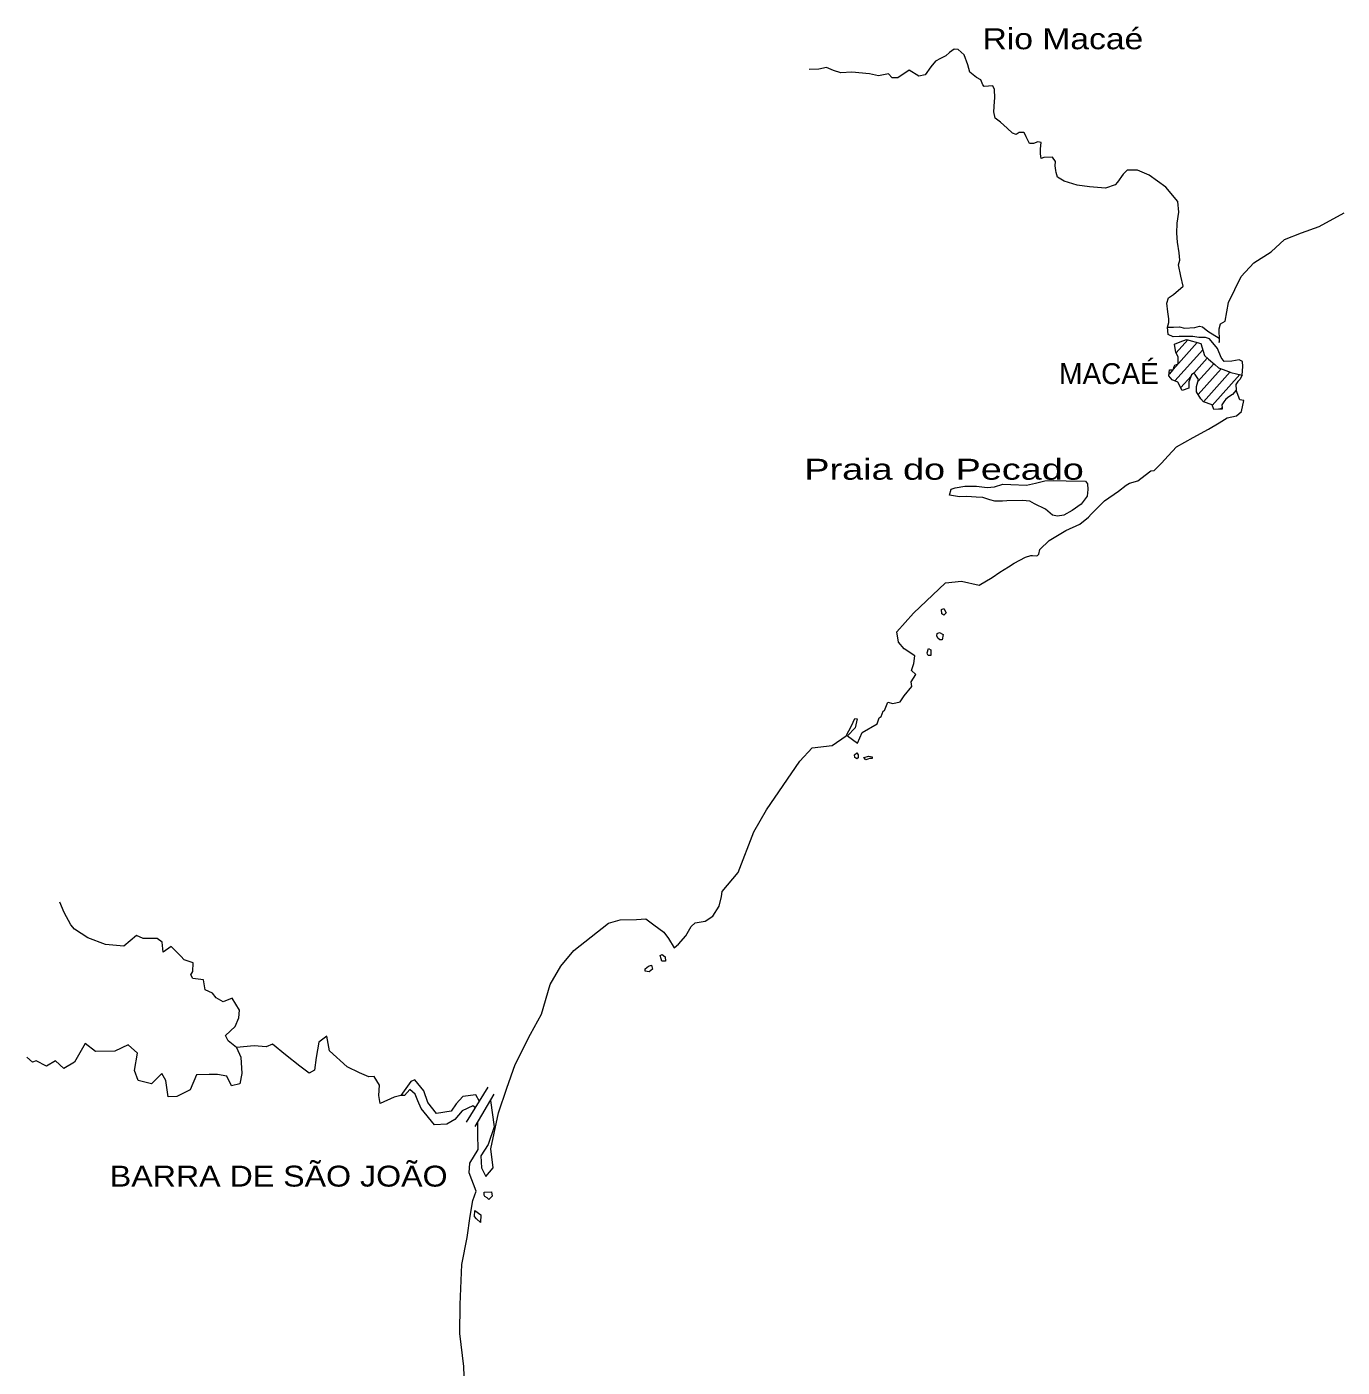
# Model space of a CAD drawing. Extents: x 47169 to 972804, y 7447977 to 9608469.
# Drawn here: x 178508 to 218240, y 7492492 to 7532969 of the extents above; entities that cross this region are included whole.
import ezdxf

# ---------------------------------------------------------------- set-up
doc = ezdxf.new("R2010")
doc.units = 0
doc.header["$LTSCALE"] = 270
doc.layers.add('1', color=7, linetype='Continuous', lineweight=13)
doc.layers.add('3', color=7, linetype='Continuous')

msp = doc.modelspace()

# ---------------------------------------------------------------- linework, layer by layer
at = {"layer": '1'}
for p, q in [((213862.1, 7523435.8), (213135, 7522624.4)), ((214031.1, 7523217.2), (213182.5, 7522281.7)), ((213582.2, 7523519.2), (213228.8, 7523124.8)), ((214159.4, 7522964.7), (213755.4, 7522513.9)), ((214358.4, 7522791), (213883.8, 7522261.4)), ((213124.9, 7522613.1), (213014, 7522478)), ((213674.6, 7522423.8), (213361.6, 7522074.4)), ((214588, 7522640.1), (213891.2, 7521862.6)), ((214857.7, 7522545.4), (214049.8, 7521643.9)), ((215147.6, 7522473.1), (214309.4, 7521537.8)), ((214609.6, 7521465.8), (214569.2, 7521420.7)), ((191788.1, 7499889.7), (192446.3, 7500944.8)), ((192048, 7499761.9), (192625.5, 7500737.8))]:
    msp.add_line(p, q, dxfattribs=at)
for points in [[(215220.2, 7522452.3), (215236.1, 7522707.5), (215233.2, 7522862.6), (215129.2, 7522916.1), (214903.3, 7522867.6), (214676.6, 7522863.4), (214581.6, 7522983.6), (214473.5, 7523258.6), (214231.2, 7523542.3), (214106.7, 7523584.3), (213910.8, 7523591.8), (213724.7, 7523621.6), (213508.3, 7523617.6), (213312.5, 7523614), (213137.3, 7523610.7), (212981.5, 7523674.4), (212967.1, 7523895.7), (213005.7, 7524040.5), (213003.6, 7524151.3), (212968.8, 7524361.2), (212943.3, 7524626.7), (212991.9, 7524782.8), (213144.6, 7524885.4), (213439, 7525134.6), (213361.1, 7525443.5), (213292.9, 7525785.8), (213331.7, 7525919.5), (213317.3, 7526140.9), (213270.1, 7526461.4), (213244.4, 7526738), (213259.5, 7527037.5), (213304.9, 7527370.8), (213278.3, 7527691.7), (212909.4, 7528128.2), (212407.9, 7528484.6), (212054.3, 7528644.3), (211745.1, 7528638.5), (211623.7, 7528514.4), (211452.8, 7528278.5), (211382, 7528199.6), (211095.3, 7528094.5), (210609.8, 7528140.9), (210237.7, 7528189.3), (209843.7, 7528303.9), (209645.4, 7528433.2), (209601.7, 7528565.4), (209590.1, 7528631.6), (209566.8, 7528775.3), (209585.2, 7528897.5), (209489.9, 7529028.7), (209232.2, 7529023.9), (209150.4, 7528989.1), (209127, 7529132.8), (209124.1, 7529287.9), (209151.5, 7529476.8), (209048, 7529497), (208914.9, 7529450.2), (208791.1, 7529447.9), (208694.6, 7529645.6), (208641, 7529755.4), (208609.7, 7529777), (208486, 7529774.6), (208394.2, 7529717.5), (208280, 7529759.7), (208122.5, 7529911.9), (207923.2, 7530085.5), (207755.8, 7530215.3), (207721.3, 7530403.1), (207736.1, 7530713.7), (207744.4, 7530824.7), (207739.6, 7531079.5), (207685.9, 7531189.3), (207428.6, 7531162.3), (207386.3, 7531216.9), (207321.5, 7531370.8), (207196.6, 7531435), (206997.6, 7531597.5), (206931.5, 7531817.9), (206822.6, 7532126.2), (206644.1, 7532289), (206515.2, 7532292.2), (206374.6, 7532196.4), (206265.3, 7532087.9), (206103.7, 7532016.2), (205958.9, 7531929.2)], [(205958.9, 7531929.2), (205810.5, 7531755.7), (205647, 7531514.3), (205452.7, 7531478.5), (205160.5, 7531661.4), (204814.1, 7531433.2), (204649.2, 7531430), (204533.5, 7531549.8), (204235.5, 7531488.7), (203966.2, 7531550), (203429, 7531595.2), (203099.3, 7531577.8), (202871, 7531651.1), (202663.1, 7531735.8), (202426.8, 7531686.9), (202138.1, 7531681.4)], [(212967.1, 7523895.7), (213142.3, 7523899), (213327.6, 7523913.5), (213472.6, 7523871.9), (213791.9, 7523888.8), (213925.2, 7523924.5), (214018.4, 7523904.1), (214185.7, 7523774.2), (214519.3, 7523569.8), (214521.8, 7523436.8), (214531.2, 7523481.3), (214524.5, 7523846.9), (214562.9, 7524002.8), (214705.7, 7524083), (214808.9, 7524639), (215186, 7525432.8), (215570.3, 7525838.8), (216090, 7526169.7), (216495.5, 7526542.8), (217007.2, 7526751.7), (217539.9, 7526938.7), (218295.3, 7527351.4)], [(206260.7, 7516179.2), (206737.8, 7516228.2), (207269.7, 7516108.6), (207667.2, 7516337.8), (207901.2, 7516497.4), (208155.7, 7516657.3), (208328.7, 7516771.4), (208675.6, 7516955.3), (208839.6, 7517002.7), (208880.8, 7517003.5), (209004.6, 7516994.8), (209035.3, 7517006.4), (209075.8, 7517040.4), (209104, 7517185), (209387.4, 7517456.4), (209897.1, 7517754.1), (210315.9, 7517950.4), (210579.7, 7518165.9), (210660.5, 7518256), (211065.3, 7518651.5), (211482.2, 7518947.5), (211715.9, 7519129.1), (211817.8, 7519186.5), (212063.8, 7519257.5), (212287.4, 7519427.9), (212460, 7519564.1), (212563, 7519566), (212785.6, 7519791.8), (212987.5, 7520017.2), (213240.1, 7520287.9), (213740, 7520563.1), (214199.1, 7520815.4), (214525.3, 7521009.9), (214769.9, 7521158.4), (215047, 7521219), (215199.1, 7521354.8), (215265.1, 7521688.4), (215151.4, 7521708.5), (215032.8, 7521994.5), (214921.7, 7521870.5), (214820.1, 7521791.1), (214728.6, 7521722.9), (214668.2, 7521644.2), (214608, 7521554.4), (214609.6, 7521465.8), (214610.4, 7521421.5), (214507.4, 7521419.6), (214363.2, 7521416.9), (214309.2, 7521548.9), (214049.8, 7521643.9), (213965.7, 7521731), (213838, 7521950.3), (213835.1, 7522105.4), (213903.4, 7522317.2), (213797.5, 7522470.4), (213755.4, 7522513.9), (213684.3, 7522457.2), (213605.8, 7522245.2), (213609.3, 7522056.9), (213404.5, 7521986.6), (213276.1, 7522239.1), (213099.5, 7522313.4), (213004.5, 7522433.5), (213021.8, 7522611.2), (213135.2, 7522613.3), (213164.2, 7522713.6), (213184.2, 7522747.2), (213286.4, 7522793.4), (213282.6, 7523003.9), (213218.3, 7523135.7), (213172.3, 7523389.7), (213346.3, 7523459.5), (213540.8, 7523529.5), (213965.7, 7523404.4), (214085.8, 7523040.9), (214201.2, 7522932.2), (214389.8, 7522769.5), (214504.9, 7522671.8), (214754.1, 7522576.7), (214878.5, 7522534.7), (215220.2, 7522452.3), (215150.5, 7522318), (215089.7, 7522261.5), (215029.5, 7522171.7), (215032.8, 7521994.5)], [(192376.9, 7498249.8), (192598.1, 7498509.2), (192524.8, 7499084.2), (192760.3, 7500175.2), (193002.7, 7500922.7), (193256.1, 7501637.2), (193721.9, 7502544.4), (194049.5, 7503149.5), (194319.9, 7504052.7), (194638.4, 7504602.2), (195030.6, 7505075.5), (196074.8, 7505905.4), (196433.4, 7506001.1), (196927.5, 7506010.9), (197205.2, 7506027.4), (197445.4, 7505854.8), (197748.5, 7505628), (197886, 7505442.3), (198066.7, 7505157.6), (198188, 7505270.9), (198409.7, 7505519.1), (198579.2, 7505799.5), (198700.6, 7505912.7), (198998.2, 7505962.9), (199232.1, 7506111.6), (199421.9, 7506414.5), (199488.3, 7506704), (199516.2, 7506859.8), (199999.3, 7507434.5), (200469.7, 7508662.9), (200848.2, 7509324.2), (201859.9, 7510795.8), (202233.4, 7511190.9), (202829.4, 7511268.9), (203256.5, 7511554.2), (203415.5, 7511856.5), (203514.2, 7512080.1), (203586.5, 7512070.4), (203529.8, 7511803.3), (203297.7, 7511555), (203600.6, 7511339.2), (203738.5, 7511663.3), (204197.2, 7511915.9), (204255.4, 7512105.4), (204316.5, 7512139.9), (204375.1, 7512307.2), (204416.1, 7512319.1), (204514.2, 7512575.9), (204669.5, 7512534.5), (204884.9, 7512583), (205005.1, 7512762.6), (205236.6, 7513044.2), (205223.6, 7513188), (205363.5, 7513412.3), (205227.3, 7513531.7), (205305.7, 7513743.7), (205332.1, 7513977), (205008.9, 7514181.4), (204840.1, 7514388.7), (204782.6, 7514698), (205287, 7515261.8), (206260.7, 7516179.2)], [(192176.9, 7500518.2), (192070, 7500715.6), (191679.9, 7500663.4), (191478.3, 7500448.7), (191328.4, 7500224), (190887.3, 7500148.6), (190623.1, 7500486.9), (190502.7, 7500839.2), (190228.5, 7501166.2), (190105.9, 7501119.4), (189805.6, 7500692.1), (189600.7, 7500643.6), (189182.4, 7500457.8), (189136.3, 7500700.8), (189160.9, 7501011.6), (189001.1, 7501274.4), (188836.7, 7501260), (188556.3, 7501376.3), (188182, 7501557.1), (187647, 7502045), (187565.9, 7502486.8), (187332.8, 7502304.7), (187249.5, 7501848.5), (187195.6, 7501459.4), (187032.8, 7501367.4), (186750.4, 7501583.4), (186321.2, 7501929.3), (185933.8, 7502242.9), (185739.8, 7502161.3), (185378.7, 7502198.2), (184844.4, 7502142.9), (184593.1, 7502348.4), (184507.3, 7502512.9), (184800.4, 7502785), (184908.3, 7503042.2), (184934.4, 7503275.5), (184710.8, 7503636.7), (184435.1, 7503520.2), (184226.5, 7503649), (184120.6, 7503790.9), (183892.1, 7503886), (183844.8, 7504184.3), (183524.6, 7504233.1), (183460.5, 7504342.7), (183520.2, 7504443.7), (183535.6, 7504699), (183265.9, 7504793.2), (183160.6, 7504901.9), (182866.2, 7505195.1), (182622.6, 7505023.8), (182595.9, 7505322.5), (182449.2, 7505441.5), (182027.1, 7505432.7), (181819.2, 7505528.2), (181434.4, 7505209.8), (180887.6, 7505253.9), (180348, 7505453.3), (179951, 7505722.2), (179835, 7505852.8), (179631.5, 7506225.5), (179501.5, 7506533.2)], [(184844.4, 7502142.9), (184973.9, 7501857.4), (185004.7, 7501359.2), (184939, 7501047.4), (184693.1, 7500986.9), (184553.2, 7501283.4), (184263.9, 7501332.9), (184016.9, 7501327.8), (183636.1, 7501319.9), (183439.4, 7500872.4), (183042.2, 7500664.7), (182774.6, 7500659.2), (182702.8, 7501145.5), (182585, 7501364.7), (182272.4, 7501047.9), (181868.7, 7501150.3), (181759.6, 7501447.4), (181851.7, 7501970.3), (181568.3, 7502230.5), (181170.8, 7502033.8), (180584.1, 7502021.6), (180270, 7502270), (179952.5, 7501698), (179626.8, 7501513.9), (179375, 7501741.4), (179100.3, 7501580.5), (178788.1, 7501740.2), (178675.5, 7501704.6), (178507.6, 7501856.3)], [(192057.2, 7500327.4), (191984.1, 7500381.3), (191657.7, 7500230.7), (191436.4, 7499971.3), (191192.1, 7499833.3), (190821.9, 7499814.8), (190420.8, 7500305.5), (190323.5, 7500536.3), (190237.2, 7500734.1), (190079.9, 7500875), (189918.8, 7500694.4), (189805.6, 7500692.1)], [(192516.1, 7500547.2), (192624.7, 7499751.3), (192439.9, 7499215.5), (192220.2, 7498878.5), (192237.8, 7498513.1), (192376.9, 7498249.8)], [(192076.9, 7497811.5), (191870.3, 7498361.6), (191885.1, 7498650.1), (192144.4, 7499065.4), (192135, 7499530.8), (192127.6, 7499896.5)], [(191738.3, 7491630.4), (191710.1, 7492516.6), (191587.2, 7493511.8), (191600.4, 7494387.8), (191648, 7495597), (191806.6, 7496409.4), (191896.6, 7497054.1), (191979.8, 7497521.4), (192076.9, 7497811.5)]]:
    msp.add_lwpolyline(points, dxfattribs=at)
for points in [[(209836.8, 7518218.4), (209641.5, 7518192.6), (209486.4, 7518223), (209276.8, 7518407.4), (208944, 7518567.4), (208808.7, 7518642.4), (208581.6, 7518660.3), (208107.8, 7518651.4), (207984.1, 7518649), (207747.2, 7518644.6), (207591.9, 7518686), (207384.4, 7518759.6), (207188.4, 7518767), (206899.6, 7518783.7), (206683.2, 7518779.6), (206383.4, 7518829.3), (206431.6, 7519007.5), (206554.6, 7519043.1), (206842.2, 7519092.9), (207058.5, 7519097), (207192.4, 7519099.5), (207512.6, 7519061.3), (207739, 7519076.6), (207984.8, 7519158.9), (208232.3, 7519152.5), (208706.8, 7519128.2), (208973.6, 7519188.6), (209260.8, 7519260.5), (209528.6, 7519265.5), (209899.7, 7519261.4), (210487.3, 7519250.3), (210550.8, 7519162.8), (210553.9, 7518996.6), (210537, 7518796.8), (210356.1, 7518549.6), (210081.3, 7518367.1)], [(206142.5, 7515244.8), (206139.9, 7515377.8), (206211.6, 7515401.3), (206275.9, 7515269.5), (206205.1, 7515201.7)], [(205997.1, 7514575), (206010.6, 7514644.2), (206081.1, 7514678.4), (206185.4, 7514613.9), (206157.4, 7514458.2), (206085.3, 7514456.9), (206022.5, 7514511.1)], [(205717.1, 7514024.3), (205701.4, 7514061.6), (205740.1, 7514195.4), (205813, 7514152.4), (205816.2, 7513986.2), (205733.8, 7513984.7)], [(203578.8, 7510862.2), (203516.2, 7510905.3), (203504.4, 7510982.7), (203575.4, 7511039.4), (203617.7, 7510984.8), (203619.4, 7510896.2)], [(203959.8, 7510869.5), (203908.5, 7510857.4), (203847.2, 7510834.1), (203794.4, 7510899.6), (203937.7, 7510946.7), (204041.1, 7510926.5), (204042.2, 7510871.1)], [(197284.8, 7504599.1), (197376.8, 7504634.2), (197410.1, 7504512.9), (197308.7, 7504433.3), (197184.7, 7504453.1), (197183.4, 7504519.5)], [(197671.6, 7504828.4), (197638.7, 7504927.5), (197700, 7504950.9), (197794, 7504886.3), (197796.6, 7504753.3), (197693.7, 7504751.3)], [(192410.4, 7497607.6), (192347.8, 7497650.7), (192326.5, 7497683.5), (192324.7, 7497772.2), (192540.6, 7497787.6), (192563.8, 7497655), (192462.9, 7497553.2)], [(192093.8, 7496969.4), (192030.6, 7497045.7), (192037.3, 7497223.2), (192225.1, 7497094), (192209.2, 7496860.9)]]:
    msp.add_lwpolyline(points, close=True, dxfattribs=at)

# ---------------------------------------------------------------- texts
at = {"layer": '3'}
for s, height, width, p in [('Rio Macaé', 633, 1.2, (207376.4, 7532291.8)), ('Praia do Pecado', 632.4, 1.35, (201993.8, 7519292.3)), ('BARRA DE SÃO JOÃO', 631.7, 1.15, (181015.1, 7497945.7))]:
    msp.add_text(s, height=height, dxfattribs=dict(at, width=width)).set_placement(p)
msp.add_text('MACAÉ', height=632.5, dxfattribs=at).set_placement((209690.6, 7522179.3))

doc.saveas('drawing.dxf')
